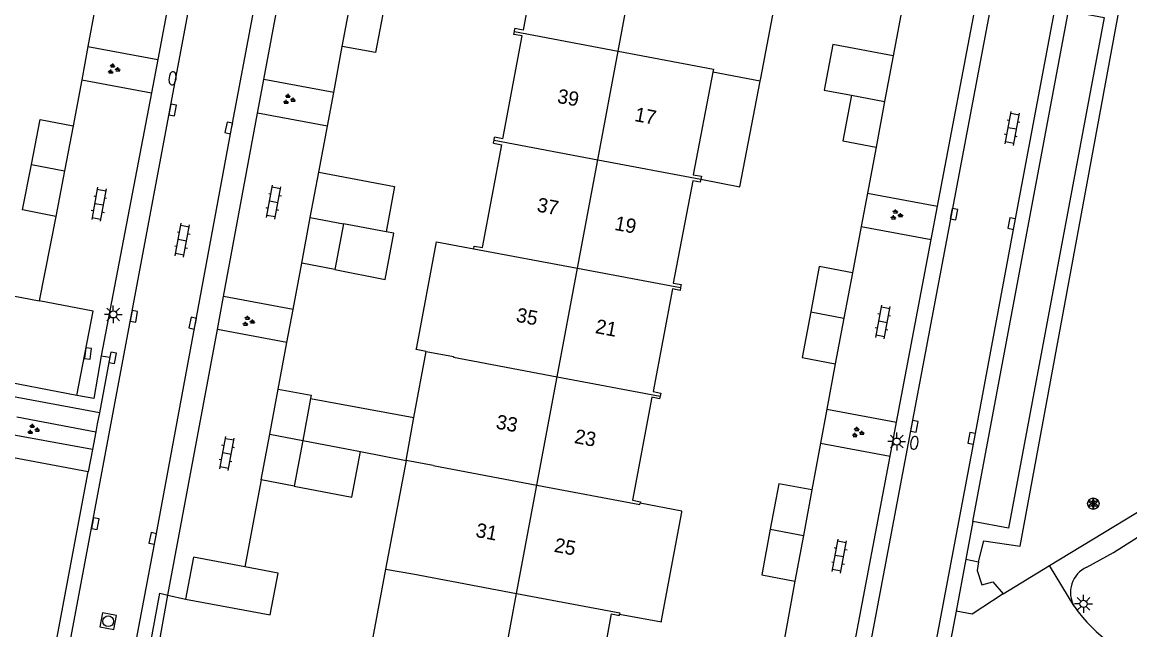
# Model space of a CAD drawing. Extents: x 124000 to 128010, y 398999 to 403000.
# Drawn here: x 126858.2 to 126935.6, y 399356.2 to 399398.6 of the extents above; entities that cross this region are included whole.
import ezdxf

# ---------------------------------------------------------------- set-up
doc = ezdxf.new("R2010")
doc.units = 0
for name, color, linetype in [('gg-afsc-hekwerk', 7, 'Continuous'), ('gg-afsc-muur', 7, 'Continuous'), ('gg-anno-huisnummerreeks BGT', 7, 'Continuous'), ('gg-bbg-bijgebouw', 7, 'Continuous'), ('gg-bbg-gedigitaliseerde bijgebouw', 7, 'Continuous'), ('gg-bbg-hoofdgebouw', 7, 'Continuous'), ('gg-bbg-luifel en loopbrug', 7, 'Continuous'), ('gg-bbg-tussenscheiding', 7, 'Continuous'), ('gg-knt-verharding', 7, 'Continuous'), ('gg-knt-verharding nz', 7, 'Continuous'), ('gt-grn-groengrens', 7, 'Continuous'), ('gt-grn-vlakafsluiter', 7, 'Continuous'), ('gt-symb-brandkraan', 7, 'Continuous'), ('gt-symb-groenvak', 7, 'Continuous'), ('gt-symb-klinker verharding', 7, 'Continuous'), ('gt-symb-kolk', 7, 'Continuous'), ('gt-symb-lichtmast', 7, 'Continuous'), ('gt-symb-rioolschacht', 7, 'Continuous'), ('gt-symb-solitaire heester', 7, 'Continuous')]:
    doc.layers.add(name, color=color, linetype=linetype)

# ---------------------------------------------------------------- blocks, each defined once
blk = doc.blocks.new('gt0-KL1')
at = {"layer": 'gt-symb-klinker verharding'}
for p, q in [((-1.15, 0.3), (1.15, 0.3)), ((-1, -0.3), (-1, 0.3)), ((-0.5, 0.3), (-0.5, 0.45)), ((0, -0.3), (0, 0.3)), ((0.5, 0.3), (0.5, 0.45)), ((1, -0.3), (1, 0.3)), ((-1.15, -0.3), (1.15, -0.3)), ((-0.5, -0.45), (-0.5, -0.3)), ((0.5, -0.45), (0.5, -0.3))]:
    blk.add_line(p, q, dxfattribs=at)
blk = doc.blocks.new('gt0-KOLK')
at = {"layer": 'gt-symb-kolk'}
blk.add_lwpolyline([(0, 0), (0.375, 0), (0.375, 0.4), (-0.375, 0.4), (-0.375, 0), (0, 0)], dxfattribs=at)
blk = doc.blocks.new('gt0-SH')
at = {"layer": 'gt-symb-solitaire heester'}
blk.add_circle((0, 0), 0.4, dxfattribs=at)
for centre, start, end in [((-0.346, 0.2), 270, 30), ((-0.346, -0.2), 330, 90), ((0, 0.4), 210, 330), ((0.346, 0.2), 150, 270), ((0.346, -0.2), 90, 210), ((0, -0.4), 30, 150)]:
    blk.add_arc(centre, 0.4, start, end, dxfattribs=at)
blk = doc.blocks.new('gt0-LMAST')
at = {"layer": 'gt-symb-lichtmast'}
for p, q in [((-0.182, 0.173), (-0.447, 0.438)), ((-0.005, 0.246), (-0.005, 0.621)), ((0.172, 0.173), (0.437, 0.438)), ((-0.255, -0.004), (-0.63, -0.004)), ((-0.182, -0.181), (-0.447, -0.446)), ((-0.005, -0.254), (-0.005, -0.629)), ((0.437, -0.446), (0.172, -0.181)), ((0.245, -0.004), (0.62, -0.004))]:
    blk.add_line(p, q, dxfattribs=at)
blk.add_circle((-0.005, -0.004), 0.25, dxfattribs=at)
blk = doc.blocks.new('gt0-GRVAK')
at = {"layer": 'gt-symb-groenvak'}
for p, q in [((-0.11, 0.189), (-0.228, 0.24)), ((-0.182, 0.153), (0.088, 0.153)), ((-0.091, 0.211), (-0.156, 0.322)), ((-0.047, 0.214), (-0.047, 0.393)), ((-0.004, 0.211), (0.061, 0.322)), ((0.015, 0.189), (0.133, 0.24)), ((0.262, -0.052), (0.197, 0.059)), ((0.305, -0.049), (0.305, 0.13)), ((0.349, -0.052), (0.414, 0.059)), ((-0.245, -0.228), (-0.363, -0.177)), ((-0.318, -0.264), (-0.047, -0.264)), ((-0.226, -0.206), (-0.291, -0.095)), ((-0.183, -0.203), (-0.183, -0.024)), ((-0.139, -0.206), (-0.074, -0.095)), ((-0.12, -0.228), (-0.002, -0.177)), ((0.243, -0.074), (0.125, -0.023)), ((0.17, -0.11), (0.441, -0.11)), ((0.368, -0.074), (0.486, -0.023))]:
    blk.add_line(p, q, dxfattribs=at)
blk = doc.blocks.new('gt0-BR')
at = {"layer": 'gt-symb-brandkraan'}
for centre, radius, start, end in [((-0.244, 0), 0.206, 107.56694, 252.43307), ((0.599, -2.664), 3, 106.89205, 107.56694), ((0, -0.691), 0.938, 73.10799, 106.89205), ((-0.599, -2.664), 3, 72.43309, 73.10799), ((0.244, 0), 0.206, 287.56695, 72.43309), ((0.599, 2.664), 3, 252.43307, 253.10797), ((0, 0.691), 0.938, 253.10797, 286.89206), ((-0.599, 2.664), 3, 286.89206, 287.56695)]:
    blk.add_arc(centre, radius, start, end, dxfattribs=at)
blk = doc.blocks.new('gt0-RS')
at = {"layer": 'gt-symb-rioolschacht'}
blk.add_lwpolyline([(-0.5, -0.5), (0.5, -0.5), (0.5, 0.5), (-0.5, 0.5)], close=True, dxfattribs=at)
blk.add_circle((0, 0), 0.375, dxfattribs=at)

msp = doc.modelspace()

# ---------------------------------------------------------------- linework, layer by layer
at = {"layer": 'gg-afsc-hekwerk'}
for p, q in [((126862.844, 399371.481), (126846.35, 399374.538)), ((126867.69, 399354.846), (126868.366, 399358.605)), ((126868.366, 399358.605), (126869.6, 399358.334))]:
    msp.add_line(p, q, dxfattribs=at)
at = {"layer": 'gg-afsc-muur'}
for p, q in [((126920.672, 399405.086), (126919.018, 399396.283)), ((126863.386, 399400.195), (126862.779, 399396.913)), ((126862.779, 399396.913), (126862.349, 399394.592)), ((126879.941, 399393.706), (126880.545, 399396.93)), ((126862.349, 399394.592), (126861.754, 399391.377)), ((126879.504, 399391.366), (126879.941, 399393.706)), ((126878.902, 399388.152), (126879.504, 399391.366)), ((126917.832, 399389.903), (126917.225, 399386.69)), ((126917.225, 399386.69), (126916.785, 399384.361)), ((126860.529, 399385.061), (126859.366, 399379.17)), ((126916.785, 399384.361), (126916.174, 399381.127)), ((126877.107, 399378.559), (126877.712, 399381.793)), ((126876.674, 399376.249), (126877.107, 399378.559)), ((126876.067, 399373.005), (126876.674, 399376.249)), ((126914.981, 399374.773), (126914.391, 399371.587)), ((126914.391, 399371.587), (126913.953, 399369.217)), ((126913.953, 399369.217), (126913.35, 399365.959)), ((126874.878, 399366.655), (126873.741, 399360.581)), ((126912.151, 399359.593), (126911.069, 399353.665))]:
    msp.add_line(p, q, dxfattribs=at)
at = {"layer": 'gg-bbg-bijgebouw'}
for p, q in [((126880.545, 399396.93), (126881.142, 399400.115)), ((126882.865, 399396.495), (126880.545, 399396.93)), ((126919.018, 399396.283), (126918.424, 399393.088)), ((126918.424, 399393.088), (126917.832, 399389.903)), ((126861.754, 399391.377), (126861.146, 399388.242)), ((126915.512, 399390.334), (126917.832, 399389.903)), ((126861.146, 399388.242), (126860.529, 399385.061)), ((126878.308, 399384.978), (126878.902, 399388.152)), ((126877.712, 399381.793), (126878.308, 399384.978)), ((126880.032, 399381.359), (126877.712, 399381.793)), ((126916.174, 399381.127), (126915.579, 399377.957)), ((126915.579, 399377.957), (126914.981, 399374.773)), ((126875.474, 399369.84), (126876.067, 399373.005)), ((126878.334, 399372.341), (126877.784, 399369.407)), ((126874.878, 399366.655), (126875.474, 399369.84)), ((126877.188, 399366.222), (126874.878, 399366.655)), ((126913.35, 399365.959), (126912.751, 399362.777)), ((126912.751, 399362.777), (126912.151, 399359.593))]:
    msp.add_line(p, q, dxfattribs=at)
for points in [[(126858.83, 399388.691), (126859.439, 399391.826), (126861.754, 399391.377)], [(126860.529, 399385.061), (126858.213, 399385.51), (126858.83, 399388.691)], [(126916.174, 399381.127), (126913.864, 399381.561), (126913.269, 399378.391)], [(126862.012, 399372.561), (126855.952, 399373.719), (126857.071, 399379.611), (126859.366, 399379.17)], [(126862.012, 399372.561), (126863.136, 399378.445), (126859.366, 399379.17)], [(126913.269, 399378.391), (126912.671, 399375.207), (126914.981, 399374.773)], [(126876.067, 399373.005), (126878.377, 399372.572), (126878.334, 399372.341)], [(126913.35, 399365.959), (126911.041, 399366.394), (126910.442, 399363.212)], [(126910.442, 399363.212), (126909.842, 399360.028), (126912.151, 399359.593)], [(126873.741, 399360.581), (126870.143, 399361.251), (126869.6, 399358.334)], [(126869.6, 399358.334), (126875.515, 399357.233), (126876.058, 399360.149), (126873.741, 399360.581)]]:
    msp.add_lwpolyline(points, dxfattribs=at)
at = {"layer": 'gg-bbg-gedigitaliseerde bijgebouw'}
for p, q in [((126883.462, 399399.68), (126882.865, 399396.495)), ((126916.104, 399393.519), (126915.512, 399390.334)), ((126880.628, 399384.544), (126880.032, 399381.359)), ((126883.597, 399383.986), (126880.628, 399384.544)), ((126877.784, 399369.407), (126881.818, 399368.632))]:
    msp.add_line(p, q, dxfattribs=at)
for points in [[(126919.018, 399396.283), (126914.814, 399397.068), (126914.213, 399393.874), (126916.104, 399393.519)], [(126878.902, 399388.152), (126884.194, 399387.159), (126883.597, 399383.986)], [(126877.188, 399366.222), (126881.207, 399365.45), (126881.818, 399368.632)]]:
    msp.add_lwpolyline(points, dxfattribs=at)
at = {"layer": 'gg-bbg-hoofdgebouw'}
for p, q in [((126909.774, 399394.719), (126911.225, 399402.283)), ((126892.562, 399397.974), (126892.599, 399398.176)), ((126909.733, 399394.508), (126906.424, 399395.142)), ((126909.733, 399394.508), (126909.774, 399394.719)), ((126891.146, 399390.379), (126891.184, 399390.589)), ((126891.762, 399390.482), (126891.184, 399390.589)), ((126891.108, 399390.171), (126891.146, 399390.379)), ((126891.108, 399390.171), (126891.685, 399390.066)), ((126887.121, 399383.278), (126889.722, 399382.791)), ((126885.546, 399371.011), (126886.399, 399375.636)), ((126884.995, 399368.021), (126885.546, 399371.011)), ((126884.995, 399368.021), (126883.572, 399360.428)), ((126902.848, 399356.828), (126904.25, 399364.394))]:
    msp.add_line(p, q, dxfattribs=at)
for points in [[(126894.5, 399405.316), (126893.187, 399398.069), (126892.599, 399398.176)], [(126891.762, 399390.482), (126893.097, 399397.67), (126892.526, 399397.773), (126892.562, 399397.974)], [(126906.424, 399395.142), (126905.049, 399387.966), (126905.624, 399387.865), (126905.587, 399387.658)], [(126889.722, 399382.791), (126889.756, 399382.989), (126890.328, 399382.891), (126891.685, 399390.066)], [(126905.587, 399387.658), (126905.55, 399387.45), (126905.022, 399387.55), (126903.663, 399380.387), (126904.205, 399380.293), (126904.17, 399380.089)], [(126886.399, 399375.636), (126885.711, 399375.765), (126885.742, 399375.922), (126887.121, 399383.278)], [(126904.17, 399380.089), (126904.134, 399379.885), (126903.599, 399379.991), (126902.251, 399372.824), (126902.79, 399372.715), (126902.75, 399372.516)], [(126902.75, 399372.516), (126902.709, 399372.316), (126902.161, 399372.425), (126900.814, 399365.247)], [(126900.814, 399365.247), (126901.373, 399365.136), (126901.351, 399365.025)], [(126904.25, 399364.394), (126904.267, 399364.485), (126901.351, 399365.025)], [(126883.572, 399360.428), (126882.143, 399352.801), (126884.072, 399352.448)], [(126893.924, 399350.595), (126898.504, 399349.733), (126898.615, 399350.135), (126898.075, 399350.284), (126899.34, 399357.308)], [(126899.34, 399357.308), (126899.897, 399357.18), (126899.915, 399357.283)], [(126899.915, 399357.283), (126902.832, 399356.744), (126902.848, 399356.828)]]:
    msp.add_lwpolyline(points, dxfattribs=at)
at = {"layer": 'gg-bbg-luifel en loopbrug'}
for p, q in [((126878.334, 399372.341), (126885.546, 399371.011)), ((126881.818, 399368.632), (126884.995, 399368.021))]:
    msp.add_line(p, q, dxfattribs=at)
for points in [[(126905.587, 399387.658), (126908.316, 399387.134), (126909.733, 399394.508)], [(126880.032, 399381.359), (126883.532, 399380.65), (126884.14, 399383.884), (126883.597, 399383.986)]]:
    msp.add_lwpolyline(points, dxfattribs=at)
at = {"layer": 'gg-bbg-tussenscheiding'}
for p, q in [((126899.805, 399396.604), (126901.221, 399404.167)), ((126892.562, 399397.974), (126899.805, 399396.604)), ((126898.384, 399389.015), (126899.805, 399396.604)), ((126916.104, 399393.519), (126918.424, 399393.088)), ((126891.146, 399390.379), (126898.384, 399389.015)), ((126896.966, 399381.436), (126898.384, 399389.015)), ((126898.384, 399389.015), (126905.587, 399387.658)), ((126858.83, 399388.691), (126861.146, 399388.242)), ((126878.308, 399384.978), (126880.628, 399384.544)), ((126889.722, 399382.791), (126896.966, 399381.436)), ((126895.549, 399373.867), (126896.966, 399381.436)), ((126896.966, 399381.436), (126904.17, 399380.089)), ((126913.269, 399378.391), (126915.579, 399377.957)), ((126894.132, 399366.295), (126895.549, 399373.867)), ((126895.549, 399373.867), (126902.75, 399372.516)), ((126875.474, 399369.84), (126877.784, 399369.407)), ((126877.784, 399369.407), (126877.188, 399366.222)), ((126886.896, 399367.655), (126884.995, 399368.021)), ((126886.896, 399367.655), (126894.132, 399366.295)), ((126892.716, 399358.731), (126894.132, 399366.295)), ((126910.442, 399363.212), (126912.751, 399362.777)), ((126891.286, 399351.091), (126892.716, 399358.731))]:
    msp.add_line(p, q, dxfattribs=at)
for points in [[(126899.805, 399396.604), (126906.463, 399395.345), (126906.424, 399395.142)], [(126886.399, 399375.636), (126888.317, 399375.282), (126888.306, 399375.225), (126895.549, 399373.867)], [(126894.132, 399366.295), (126901.335, 399364.942), (126901.351, 399365.025)], [(126883.572, 399360.428), (126885.475, 399360.09), (126892.716, 399358.731)], [(126892.716, 399358.731), (126899.931, 399357.376), (126899.915, 399357.283)]]:
    msp.add_lwpolyline(points, dxfattribs=at)
at = {"layer": 'gg-knt-verharding'}
for p, q in [((126922.118, 399385.765), (126928.477, 399419.328)), ((126870.096, 399408.803), (126867.651, 399396.011)), ((126875.062, 399394.619), (126877.445, 399407.44)), ((126862.779, 399396.913), (126867.651, 399396.011)), ((126867.651, 399396.011), (126867.208, 399393.693)), ((126862.349, 399394.592), (126867.208, 399393.693)), ((126874.627, 399392.279), (126875.062, 399394.619)), ((126879.941, 399393.706), (126875.062, 399394.619)), ((126867.208, 399393.693), (126863.697, 399375.326)), ((126872.245, 399379.469), (126874.627, 399392.279)), ((126879.504, 399391.366), (126874.627, 399392.279)), ((126917.225, 399386.69), (126922.118, 399385.765)), ((126921.677, 399383.437), (126922.118, 399385.765)), ((126916.785, 399384.361), (126921.677, 399383.437)), ((126919.261, 399370.686), (126921.677, 399383.437)), ((126871.815, 399377.158), (126872.245, 399379.469)), ((126877.107, 399378.559), (126872.245, 399379.469)), ((126868.366, 399358.605), (126871.815, 399377.158)), ((126876.674, 399376.249), (126871.815, 399377.158)), ((126863.093, 399368.791), (126846.447, 399371.813)), ((126863.575, 399371.343), (126862.844, 399371.481)), ((126863.575, 399371.343), (126863.429, 399370.569)), ((126914.391, 399371.587), (126919.261, 399370.686)), ((126863.429, 399370.569), (126863.325, 399370.02)), ((126918.813, 399368.318), (126919.261, 399370.686)), ((126862.797, 399367.223), (126846.411, 399370.27)), ((126863.325, 399370.02), (126863.093, 399368.791)), ((126913.953, 399369.217), (126918.813, 399368.318)), ((126863.093, 399368.791), (126862.797, 399367.223)), ((126915.337, 399349.973), (126918.813, 399368.318)), ((126858.898, 399346.588), (126862.797, 399367.223)), ((126924.586, 399363.76), (126924.09, 399361.113)), ((126924.09, 399361.113), (126923.412, 399357.491)), ((126924.09, 399361.113), (126924.989, 399360.945)), ((126926.698, 399358.704), (126929.948, 399360.676)), ((126923.412, 399357.491), (126922.302, 399351.564))]:
    msp.add_line(p, q, dxfattribs=at)
for points in [[(126859.41, 399345.721), (126859.812, 399345.958), (126860.245, 399348.522), (126874.185, 399422.789), (126876.299, 399434.381), (126882.625, 399467.842), (126888.629, 399500)], [(126864.05, 399344.335), (126867.497, 399362.533), (126872.812, 399391.194), (126881.431, 399436.976), (126887.006, 399467.005), (126893.192, 399500)], [(126944.485, 399500), (126939.587, 399473.706), (126936.837, 399458.712), (126928.724, 399415.495), (126925.981, 399400.56), (126911.09, 399321.653), (126906.668, 399319.738)], [(126918.239, 399314.105), (126915.165, 399319.891), (126916.306, 399325.001), (126924.705, 399369.522), (126927.489, 399384.524), (126938.592, 399443.591), (126941.213, 399457.849), (126949.077, 399500)], [(126931.264, 399399.421), (126933.755, 399398.954), (126927.081, 399363.293), (126924.586, 399363.76)], [(126929.948, 399360.676), (126939.707, 399366.6), (126944.946, 399369.391), (126950.187, 399371.678), (126955.154, 399373.042), (126961.64, 399374.538), (126967.759, 399376.185), (126973.042, 399377.808), (126974.551, 399378.152), (126974.932, 399377.966)], [(126932.55, 399360.559), (126934.406, 399361.591), (126940.45, 399365.395), (126945.545, 399368.109), (126950.59, 399370.147), (126956.302, 399371.659), (126962.407, 399373.15), (126964.301, 399373.647), (126969.357, 399375.289), (126972.614, 399376.026)], [(126863.697, 399375.326), (126864.308, 399375.221), (126863.575, 399371.343)], [(126924.989, 399360.945), (126924.883, 399360.336), (126925.215, 399359.325), (126925.988, 399359.549), (126926.698, 399358.704)], [(126867.091, 399354.96), (126867.795, 399358.749), (126868.366, 399358.605)], [(126926.698, 399358.704), (126924.545, 399357.278), (126923.412, 399357.491)]]:
    msp.add_lwpolyline(points, dxfattribs=at)
for centre, radius, start, end in [((126933.326, 399358.805), 1.918, 113.86874, 210.57641), ((126940.593, 399364.047), 10.871, 214.88067, 254.31097)]:
    msp.add_arc(centre, radius, start, end, dxfattribs=at)
at = {"layer": 'gg-knt-verharding nz'}
msp.add_line((126924.586, 399363.76), (126931.264, 399399.421), dxfattribs=at)
at = {"layer": 'gt-grn-groengrens'}
msp.add_line((126857.804, 399371.062), (126863.325, 399370.02), dxfattribs=at)
msp.add_lwpolyline([(126924.989, 399360.945), (126925.352, 399362.4), (126927.882, 399362.036), (126934.866, 399399.748), (126932.215, 399400.15)], dxfattribs=at)
at = {"layer": 'gt-grn-vlakafsluiter'}
for p, q in [((126863.697, 399375.326), (126863.186, 399372.34)), ((126863.186, 399372.34), (126862.012, 399372.561)), ((126931.675, 399357.83), (126929.948, 399360.676))]:
    msp.add_line(p, q, dxfattribs=at)

# ---------------------------------------------------------------- block references
at = {"layer": 'gt-symb-brandkraan'}
for p, rotation in [((126868.685, 399394.701), 82.29934460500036), ((126920.501, 399369.243), -99.66950525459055)]:
    msp.add_blockref('gt0-BR', p, dxfattribs=dict(at, rotation=rotation))
at = {"layer": 'gt-symb-groenvak'}
for p in [(126864.554, 399395.344), (126876.8, 399393.226), (126919.229, 399385.158), (126873.969, 399377.731), (126858.94, 399370.179), (126916.535, 399369.961)]:
    msp.add_blockref('gt0-GRVAK', p, dxfattribs=at)
at = {"layer": 'gt-symb-klinker verharding'}
for p, rotation in [((126927.343, 399391.2), 79.39794170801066), ((126863.544, 399385.914), -100.14079314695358), ((126875.753, 399386.057), 79.45426563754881), ((126869.374, 399383.39), 79.39794170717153), ((126918.308, 399377.684), 79.45426563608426), ((126872.488, 399368.498), 79.45426563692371), ((126915.268, 399361.33), 79.45426563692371)]:
    msp.add_blockref('gt0-KL1', p, dxfattribs=dict(at, rotation=rotation))
at = {"layer": 'gt-symb-kolk'}
for p, rotation in [((126868.489, 399392.524), -100.60205829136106), ((126872.812, 399391.194), 77.06118937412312), ((126923.08, 399385.253), -100.30997039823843), ((126927.489, 399384.524), 79.34163849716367), ((126865.787, 399378.117), -100.60205829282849), ((126870.287, 399377.562), 77.70114482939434), ((126862.584, 399375.516), -97.2387265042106), ((126864.308, 399375.221), -100.71464389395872), ((126920.307, 399370.441), -100.30997039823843), ((126924.705, 399369.522), 79.28535610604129), ((126863.091, 399363.64), -100.60205829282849), ((126867.497, 399362.533), 78.11724113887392)]:
    msp.add_blockref('gt0-KOLK', p, dxfattribs=dict(at, rotation=rotation))
at = {"layer": 'gt-symb-lichtmast'}
for p in [(126864.553, 399378.221), (126919.275, 399369.337), (126932.327, 399358.002)]:
    msp.add_blockref('gt0-LMAST', p, dxfattribs=at)
at = {"layer": 'gt-symb-rioolschacht', "rotation": 79.28535610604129}
msp.add_blockref('gt0-RS', (126864.194, 399356.786), dxfattribs=at)
at = {"layer": 'gt-symb-solitaire heester'}
msp.add_blockref('gt0-SH', (126933, 399365), dxfattribs=at)

# ---------------------------------------------------------------- texts
at = {"layer": 'gg-anno-huisnummerreeks BGT'}
for s, rotation, p in [('39', 349.5, (126895.507, 399393)), ('17', 349.2, (126900.906, 399391.726)), ('37', 349.3, (126894.085, 399385.412)), ('19', 349.3, (126899.51, 399384.123)), ('35', 349.2, (126892.631, 399377.717)), ('21', 349.3, (126898.162, 399376.92)), ('33', 349.4, (126891.225, 399370.254)), ('23', 349.4, (126896.703, 399369.241)), ('31', 349.4, (126889.81, 399362.687)), ('25', 349.5, (126895.287, 399361.644))]:
    msp.add_text(s, height=1, rotation=rotation, dxfattribs=at).set_placement(p)

doc.saveas('drawing.dxf')
